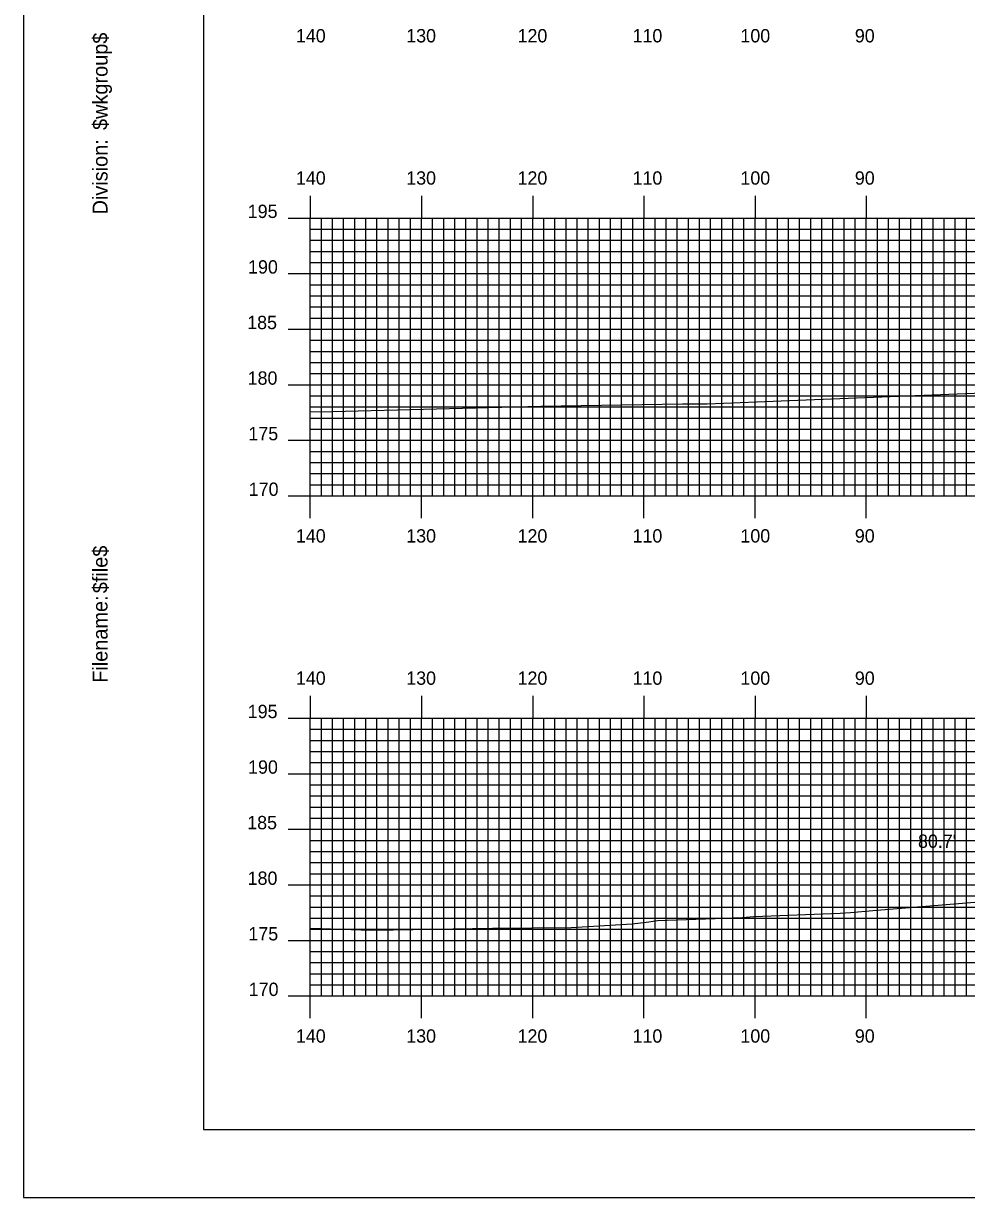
# Model space of a CAD drawing. Extents: x 1823571 to 1823914, y 442310 to 442530.
# Drawn here: x 1823571.1 to 1823655.9, y 442310 to 442415.6 of the extents above; entities that cross this region are included whole.
import ezdxf

# ---------------------------------------------------------------- set-up
doc = ezdxf.new("R2010")
doc.units = 0
for name, color, linetype in [('BORDER', 7, 'Continuous'), ('D_Text_Standard', 7, 'Continuous'), ('H_V ANNOTATION', 7, 'Continuous'), ('MAJOR', 7, 'Continuous'), ('MINOR', 7, 'Continuous'), ('PLOT BOUNDARY', 7, 'Continuous'), ('S_Roadway_Centerline', 7, 'Continuous')]:
    doc.layers.add(name, color=color, linetype=linetype)

msp = doc.modelspace()

# ---------------------------------------------------------------- linework, layer by layer
at = {"layer": 'BORDER'}
msp.add_lwpolyline([(1823587.3, 442316.11), (1823907.3, 442316.11), (1823907.3, 442526.11), (1823587.3, 442526.11)], close=True, dxfattribs=at)
at = {"layer": 'MAJOR'}
for p, q in [((1823596.9, 442400.12), (1823596.9, 442398.12)), ((1823606.9, 442400.12), (1823606.9, 442398.12)), ((1823616.9, 442400.12), (1823616.9, 442398.12)), ((1823626.9, 442400.12), (1823626.9, 442398.12)), ((1823636.9, 442400.12), (1823636.9, 442398.12)), ((1823646.9, 442400.12), (1823646.9, 442398.12)), ((1823594.9, 442398.12), (1823596.9, 442398.12)), ((1823596.9, 442398.12), (1823876.9, 442398.12)), ((1823596.9, 442373.12), (1823596.9, 442398.12)), ((1823596.9, 442373.12), (1823596.9, 442398.12)), ((1823596.9, 442398.12), (1823876.9, 442398.12)), ((1823606.9, 442373.12), (1823606.9, 442398.12)), ((1823616.9, 442373.12), (1823616.9, 442398.12)), ((1823626.9, 442373.12), (1823626.9, 442398.12)), ((1823636.9, 442373.12), (1823636.9, 442398.12)), ((1823646.9, 442373.12), (1823646.9, 442398.12)), ((1823594.9, 442393.12), (1823596.9, 442393.12)), ((1823596.9, 442393.12), (1823876.9, 442393.12)), ((1823594.9, 442388.12), (1823596.9, 442388.12)), ((1823596.9, 442388.12), (1823876.9, 442388.12)), ((1823594.9, 442383.12), (1823596.9, 442383.12)), ((1823596.9, 442383.12), (1823876.9, 442383.12)), ((1823594.9, 442378.12), (1823596.9, 442378.12)), ((1823596.9, 442378.12), (1823876.9, 442378.12)), ((1823594.9, 442373.12), (1823596.9, 442373.12)), ((1823596.9, 442371.11), (1823596.9, 442373.12)), ((1823596.9, 442373.12), (1823876.9, 442373.12)), ((1823606.9, 442371.11), (1823606.9, 442373.12)), ((1823616.9, 442371.11), (1823616.9, 442373.12)), ((1823626.9, 442371.11), (1823626.9, 442373.12)), ((1823636.9, 442371.11), (1823636.9, 442373.12)), ((1823646.9, 442371.11), (1823646.9, 442373.12)), ((1823596.9, 442355.12), (1823596.9, 442353.12)), ((1823606.9, 442355.12), (1823606.9, 442353.12)), ((1823616.9, 442355.12), (1823616.9, 442353.12)), ((1823626.9, 442355.12), (1823626.9, 442353.12)), ((1823636.9, 442355.12), (1823636.9, 442353.12)), ((1823646.9, 442355.12), (1823646.9, 442353.12)), ((1823594.9, 442353.12), (1823596.9, 442353.12)), ((1823596.9, 442328.12), (1823596.9, 442353.12)), ((1823596.9, 442328.12), (1823596.9, 442353.12)), ((1823596.9, 442353.12), (1823876.9, 442353.12)), ((1823606.9, 442328.12), (1823606.9, 442353.12)), ((1823616.9, 442328.12), (1823616.9, 442353.12)), ((1823626.9, 442328.12), (1823626.9, 442353.12)), ((1823636.9, 442328.12), (1823636.9, 442353.12)), ((1823646.9, 442328.12), (1823646.9, 442353.12)), ((1823594.9, 442348.12), (1823596.9, 442348.12)), ((1823596.9, 442348.12), (1823876.9, 442348.12)), ((1823594.9, 442343.12), (1823596.9, 442343.12)), ((1823596.9, 442343.12), (1823876.9, 442343.12)), ((1823594.9, 442338.12), (1823596.9, 442338.12)), ((1823596.9, 442338.12), (1823876.9, 442338.12)), ((1823594.9, 442333.12), (1823596.9, 442333.12)), ((1823596.9, 442333.12), (1823876.9, 442333.12)), ((1823594.9, 442328.12), (1823596.9, 442328.12)), ((1823596.9, 442328.12), (1823876.9, 442328.12)), ((1823596.9, 442328.12), (1823876.9, 442328.12)), ((1823596.9, 442326.11), (1823596.9, 442328.12)), ((1823606.9, 442326.11), (1823606.9, 442328.12)), ((1823616.9, 442326.11), (1823616.9, 442328.12)), ((1823626.9, 442326.11), (1823626.9, 442328.12)), ((1823636.9, 442326.11), (1823636.9, 442328.12)), ((1823646.9, 442326.11), (1823646.9, 442328.12))]:
    msp.add_line(p, q, dxfattribs=at)
at = {"layer": 'MINOR'}
for p, q in [((1823597.9, 442373.12), (1823597.9, 442398.12)), ((1823598.9, 442373.12), (1823598.9, 442398.12)), ((1823599.9, 442373.12), (1823599.9, 442398.12)), ((1823600.9, 442373.12), (1823600.9, 442398.12)), ((1823601.9, 442373.12), (1823601.9, 442398.12)), ((1823602.9, 442373.12), (1823602.9, 442398.12)), ((1823603.9, 442373.12), (1823603.9, 442398.12)), ((1823604.9, 442373.12), (1823604.9, 442398.12)), ((1823605.9, 442373.12), (1823605.9, 442398.12)), ((1823607.9, 442373.12), (1823607.9, 442398.12)), ((1823608.9, 442373.12), (1823608.9, 442398.12)), ((1823609.9, 442373.12), (1823609.9, 442398.12)), ((1823610.9, 442373.12), (1823610.9, 442398.12)), ((1823611.9, 442373.12), (1823611.9, 442398.12)), ((1823612.9, 442373.12), (1823612.9, 442398.12)), ((1823613.9, 442373.12), (1823613.9, 442398.12)), ((1823614.9, 442373.12), (1823614.9, 442398.12)), ((1823615.9, 442373.12), (1823615.9, 442398.12)), ((1823617.9, 442373.12), (1823617.9, 442398.12)), ((1823618.9, 442373.12), (1823618.9, 442398.12)), ((1823619.9, 442373.12), (1823619.9, 442398.12)), ((1823620.9, 442373.12), (1823620.9, 442398.12)), ((1823621.9, 442373.12), (1823621.9, 442398.12)), ((1823622.9, 442373.12), (1823622.9, 442398.12)), ((1823623.9, 442373.12), (1823623.9, 442398.12)), ((1823624.9, 442373.12), (1823624.9, 442398.12)), ((1823625.9, 442373.12), (1823625.9, 442398.12)), ((1823627.9, 442373.12), (1823627.9, 442398.12)), ((1823628.9, 442373.12), (1823628.9, 442398.12)), ((1823629.9, 442373.12), (1823629.9, 442398.12)), ((1823630.9, 442373.12), (1823630.9, 442398.12)), ((1823631.9, 442373.12), (1823631.9, 442398.12)), ((1823632.9, 442373.12), (1823632.9, 442398.12)), ((1823633.9, 442373.12), (1823633.9, 442398.12)), ((1823634.9, 442373.12), (1823634.9, 442398.12)), ((1823635.9, 442373.12), (1823635.9, 442398.12)), ((1823637.9, 442373.12), (1823637.9, 442398.12)), ((1823638.9, 442373.12), (1823638.9, 442398.12)), ((1823639.9, 442373.12), (1823639.9, 442398.12)), ((1823640.9, 442373.12), (1823640.9, 442398.12)), ((1823641.9, 442373.12), (1823641.9, 442398.12)), ((1823642.9, 442373.12), (1823642.9, 442398.12)), ((1823643.9, 442373.12), (1823643.9, 442398.12)), ((1823644.9, 442373.12), (1823644.9, 442398.12)), ((1823645.9, 442373.12), (1823645.9, 442398.12)), ((1823647.9, 442373.12), (1823647.9, 442398.12)), ((1823648.9, 442373.12), (1823648.9, 442398.12)), ((1823649.9, 442373.12), (1823649.9, 442398.12)), ((1823650.9, 442373.12), (1823650.9, 442398.12)), ((1823651.9, 442373.12), (1823651.9, 442398.12)), ((1823652.9, 442373.12), (1823652.9, 442398.12)), ((1823653.9, 442373.12), (1823653.9, 442398.12)), ((1823654.9, 442373.12), (1823654.9, 442398.12)), ((1823655.9, 442373.12), (1823655.9, 442398.12)), ((1823596.9, 442397.12), (1823876.9, 442397.12)), ((1823596.9, 442397.12), (1823598.9, 442397.12)), ((1823596.9, 442396.12), (1823876.9, 442396.12)), ((1823596.9, 442396.12), (1823598.9, 442396.12)), ((1823596.9, 442395.12), (1823876.9, 442395.12)), ((1823596.9, 442395.12), (1823598.9, 442395.12)), ((1823596.9, 442394.12), (1823876.9, 442394.12)), ((1823596.9, 442394.12), (1823598.9, 442394.12)), ((1823596.9, 442392.12), (1823876.9, 442392.12)), ((1823596.9, 442392.12), (1823598.9, 442392.12)), ((1823596.9, 442391.12), (1823876.9, 442391.12)), ((1823596.9, 442391.12), (1823598.9, 442391.12)), ((1823596.9, 442390.12), (1823876.9, 442390.12)), ((1823596.9, 442390.12), (1823598.9, 442390.12)), ((1823596.9, 442389.12), (1823876.9, 442389.12)), ((1823596.9, 442389.12), (1823598.9, 442389.12)), ((1823596.9, 442387.12), (1823598.9, 442387.12)), ((1823596.9, 442387.12), (1823876.9, 442387.12)), ((1823596.9, 442386.12), (1823876.9, 442386.12)), ((1823596.9, 442386.12), (1823598.9, 442386.12)), ((1823596.9, 442385.12), (1823876.9, 442385.12)), ((1823596.9, 442385.12), (1823598.9, 442385.12)), ((1823596.9, 442384.12), (1823876.9, 442384.12)), ((1823596.9, 442384.12), (1823598.9, 442384.12)), ((1823596.9, 442382.12), (1823876.9, 442382.12)), ((1823596.9, 442382.12), (1823598.9, 442382.12)), ((1823596.9, 442381.12), (1823876.9, 442381.12)), ((1823596.9, 442381.12), (1823598.9, 442381.12)), ((1823596.9, 442380.12), (1823876.9, 442380.12)), ((1823596.9, 442380.12), (1823598.9, 442380.12)), ((1823596.9, 442379.12), (1823876.9, 442379.12)), ((1823596.9, 442379.12), (1823598.9, 442379.12)), ((1823596.9, 442377.12), (1823876.9, 442377.12)), ((1823596.9, 442377.12), (1823598.9, 442377.12)), ((1823596.9, 442376.12), (1823876.9, 442376.12)), ((1823596.9, 442376.12), (1823598.9, 442376.12)), ((1823596.9, 442375.12), (1823876.9, 442375.12)), ((1823596.9, 442375.12), (1823598.9, 442375.12)), ((1823596.9, 442374.12), (1823876.9, 442374.12)), ((1823596.9, 442374.12), (1823598.9, 442374.12)), ((1823597.9, 442328.12), (1823597.9, 442353.12)), ((1823598.9, 442328.12), (1823598.9, 442353.12)), ((1823599.9, 442328.12), (1823599.9, 442353.12)), ((1823600.9, 442328.12), (1823600.9, 442353.12)), ((1823601.9, 442328.12), (1823601.9, 442353.12)), ((1823602.9, 442328.12), (1823602.9, 442353.12)), ((1823603.9, 442328.12), (1823603.9, 442353.12)), ((1823604.9, 442328.12), (1823604.9, 442353.12)), ((1823605.9, 442328.12), (1823605.9, 442353.12)), ((1823607.9, 442328.12), (1823607.9, 442353.12)), ((1823608.9, 442328.12), (1823608.9, 442353.12)), ((1823609.9, 442328.12), (1823609.9, 442353.12)), ((1823610.9, 442328.12), (1823610.9, 442353.12)), ((1823611.9, 442328.12), (1823611.9, 442353.12)), ((1823612.9, 442328.12), (1823612.9, 442353.12)), ((1823613.9, 442328.12), (1823613.9, 442353.12)), ((1823614.9, 442328.12), (1823614.9, 442353.12)), ((1823615.9, 442328.12), (1823615.9, 442353.12)), ((1823617.9, 442328.12), (1823617.9, 442353.12)), ((1823618.9, 442328.12), (1823618.9, 442353.12)), ((1823619.9, 442328.12), (1823619.9, 442353.12)), ((1823620.9, 442328.12), (1823620.9, 442353.12)), ((1823621.9, 442328.12), (1823621.9, 442353.12)), ((1823622.9, 442328.12), (1823622.9, 442353.12)), ((1823623.9, 442328.12), (1823623.9, 442353.12)), ((1823624.9, 442328.12), (1823624.9, 442353.12)), ((1823625.9, 442328.12), (1823625.9, 442353.12)), ((1823627.9, 442328.12), (1823627.9, 442353.12)), ((1823628.9, 442328.12), (1823628.9, 442353.12)), ((1823629.9, 442328.12), (1823629.9, 442353.12)), ((1823630.9, 442328.12), (1823630.9, 442353.12)), ((1823631.9, 442328.12), (1823631.9, 442353.12)), ((1823632.9, 442328.12), (1823632.9, 442353.12)), ((1823633.9, 442328.12), (1823633.9, 442353.12)), ((1823634.9, 442328.12), (1823634.9, 442353.12)), ((1823635.9, 442328.12), (1823635.9, 442353.12)), ((1823637.9, 442328.12), (1823637.9, 442353.12)), ((1823638.9, 442328.12), (1823638.9, 442353.12)), ((1823639.9, 442328.12), (1823639.9, 442353.12)), ((1823640.9, 442328.12), (1823640.9, 442353.12)), ((1823641.9, 442328.12), (1823641.9, 442353.12)), ((1823642.9, 442328.12), (1823642.9, 442353.12)), ((1823643.9, 442328.12), (1823643.9, 442353.12)), ((1823644.9, 442328.12), (1823644.9, 442353.12)), ((1823645.9, 442328.12), (1823645.9, 442353.12)), ((1823647.9, 442328.12), (1823647.9, 442353.12)), ((1823648.9, 442328.12), (1823648.9, 442353.12)), ((1823649.9, 442328.12), (1823649.9, 442353.12)), ((1823650.9, 442328.12), (1823650.9, 442353.12)), ((1823651.9, 442328.12), (1823651.9, 442353.12)), ((1823652.9, 442328.12), (1823652.9, 442353.12)), ((1823653.9, 442328.12), (1823653.9, 442353.12)), ((1823654.9, 442328.12), (1823654.9, 442353.12)), ((1823655.9, 442328.12), (1823655.9, 442353.12)), ((1823596.9, 442352.12), (1823876.9, 442352.12)), ((1823596.9, 442352.12), (1823598.9, 442352.12)), ((1823596.9, 442351.12), (1823876.9, 442351.12)), ((1823596.9, 442351.12), (1823598.9, 442351.12)), ((1823596.9, 442350.12), (1823876.9, 442350.12)), ((1823596.9, 442350.12), (1823598.9, 442350.12)), ((1823596.9, 442349.12), (1823876.9, 442349.12)), ((1823596.9, 442349.12), (1823598.9, 442349.12)), ((1823596.9, 442347.12), (1823876.9, 442347.12)), ((1823596.9, 442347.12), (1823598.9, 442347.12)), ((1823596.9, 442346.12), (1823876.9, 442346.12)), ((1823596.9, 442346.12), (1823598.9, 442346.12)), ((1823596.9, 442345.12), (1823876.9, 442345.12)), ((1823596.9, 442345.12), (1823598.9, 442345.12)), ((1823596.9, 442344.12), (1823876.9, 442344.12)), ((1823596.9, 442344.12), (1823598.9, 442344.12)), ((1823596.9, 442342.12), (1823876.9, 442342.12)), ((1823596.9, 442342.12), (1823598.9, 442342.12)), ((1823596.9, 442341.12), (1823876.9, 442341.12)), ((1823596.9, 442341.12), (1823598.9, 442341.12)), ((1823596.9, 442340.12), (1823876.9, 442340.12)), ((1823596.9, 442340.12), (1823598.9, 442340.12)), ((1823596.9, 442339.12), (1823876.9, 442339.12)), ((1823596.9, 442339.12), (1823598.9, 442339.12)), ((1823596.9, 442337.12), (1823876.9, 442337.12)), ((1823596.9, 442337.12), (1823598.9, 442337.12)), ((1823596.9, 442336.12), (1823876.9, 442336.12)), ((1823596.9, 442336.12), (1823598.9, 442336.12)), ((1823596.9, 442335.12), (1823876.9, 442335.12)), ((1823596.9, 442335.12), (1823598.9, 442335.12)), ((1823596.9, 442334.12), (1823876.9, 442334.12)), ((1823596.9, 442334.12), (1823598.9, 442334.12)), ((1823596.9, 442332.12), (1823876.9, 442332.12)), ((1823596.9, 442332.12), (1823598.9, 442332.12)), ((1823596.9, 442331.12), (1823876.9, 442331.12)), ((1823596.9, 442331.12), (1823598.9, 442331.12)), ((1823596.9, 442330.12), (1823876.9, 442330.12)), ((1823596.9, 442330.12), (1823598.9, 442330.12)), ((1823596.9, 442329.12), (1823876.9, 442329.12)), ((1823596.9, 442329.12), (1823598.9, 442329.12))]:
    msp.add_line(p, q, dxfattribs=at)
at = {"layer": 'PLOT BOUNDARY'}
msp.add_lwpolyline([(1823571.11, 442309.99), (1823911.11, 442309.99), (1823911.11, 442529.99), (1823571.11, 442529.99)], close=True, dxfattribs=at)
at = {"layer": 'S_Roadway_Centerline'}
for points in [[(1823596.9, 442380.67), (1823598.86, 442380.71), (1823617.63, 442381.18), (1823630.38, 442381.41), (1823632.58, 442381.4), (1823639.99, 442381.7), (1823658.85, 442382.44)], [(1823596.9, 442334.22), (1823602.42, 442334.05), (1823604.34, 442334.07), (1823613.29, 442334.21), (1823620.36, 442334.27), (1823625.84, 442334.62), (1823627.33, 442334.79), (1823628.11, 442334.92), (1823634.18, 442335.13), (1823635.73, 442335.18), (1823636.8, 442335.26), (1823644.55, 442335.57), (1823645.48, 442335.64), (1823647.5, 442335.81), (1823660.67, 442336.89)]]:
    msp.add_lwpolyline(points, dxfattribs=at)

# ---------------------------------------------------------------- texts
at = {"layer": 'BORDER'}
for s, p in [('$wkgroup$', (1823578.67, 442406.04)), ('Division:', (1823578.67, 442398.44)), ('$file$', (1823578.67, 442364.36)), ('Filename:', (1823578.67, 442356.3))]:
    msp.add_text(s, height=1.339, rotation=90, dxfattribs=at).set_placement(p)
at = {"layer": 'D_Text_Standard'}
msp.add_text("80.7'", height=1.2, dxfattribs=at).set_placement((1823651.55, 442341.45))
at = {"layer": 'H_V ANNOTATION'}
for s, p in [('140', (1823595.61, 442413.92)), ('130', (1823605.53, 442413.92)), ('120', (1823615.54, 442413.92)), ('110', (1823625.88, 442413.92)), ('100', (1823635.58, 442413.92)), ('90', (1823645.87, 442413.92)), ('140', (1823595.61, 442401.12)), ('130', (1823605.53, 442401.12)), ('120', (1823615.54, 442401.12)), ('110', (1823625.88, 442401.12)), ('100', (1823635.58, 442401.12)), ('90', (1823645.87, 442401.12)), ('195', (1823591.28, 442398.12)), ('190', (1823591.31, 442393.12)), ('185', (1823591.23, 442388.12)), ('180', (1823591.27, 442383.12)), ('175', (1823591.34, 442378.12)), ('170', (1823591.37, 442373.12)), ('140', (1823595.61, 442368.92)), ('130', (1823605.53, 442368.92)), ('120', (1823615.54, 442368.92)), ('110', (1823625.88, 442368.92)), ('100', (1823635.58, 442368.92)), ('90', (1823645.87, 442368.92)), ('140', (1823595.61, 442356.12)), ('130', (1823605.53, 442356.12)), ('120', (1823615.54, 442356.12)), ('110', (1823625.88, 442356.12)), ('100', (1823635.58, 442356.12)), ('90', (1823645.87, 442356.12)), ('195', (1823591.28, 442353.12)), ('190', (1823591.31, 442348.12)), ('185', (1823591.23, 442343.12)), ('180', (1823591.27, 442338.12)), ('175', (1823591.34, 442333.12)), ('170', (1823591.37, 442328.12)), ('140', (1823595.61, 442323.92)), ('130', (1823605.53, 442323.92)), ('120', (1823615.54, 442323.92)), ('110', (1823625.88, 442323.92)), ('100', (1823635.58, 442323.92)), ('90', (1823645.87, 442323.92))]:
    msp.add_text(s, height=1.2, dxfattribs=at).set_placement(p)
at = {"layer": 'MAJOR'}
msp.add_text('-', height=0.012, dxfattribs=at).set_placement((1823596.89, 442328.12))

doc.saveas('drawing.dxf')
